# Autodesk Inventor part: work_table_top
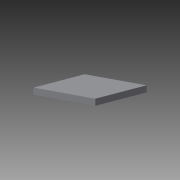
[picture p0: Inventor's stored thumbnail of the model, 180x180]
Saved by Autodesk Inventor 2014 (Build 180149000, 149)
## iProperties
Created: 2008-06
Part Number: work_table_top
Document SubType Name: Modeling
Designer: Autodesk
Density: 1 g/cm^3
Material: Generic
Appearance: Default
Author: Autodesk
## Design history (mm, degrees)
sketch "Sketch1"
  geometry: L1 (0, 0)-(1000, 0); L2 (1000, 0)-(1000, 90); L3 (1000, 90)-(0, 90); L4 (0, 90)-(0, 0)
  constraints: 8 end point, 2 parallel, 1 horizontal, 1 perpendicular
  dimensions: "d0" = 1000 distance of L2.end L3.end; "d1" = 90 distance of L3.end L1.start
extrude "Extrusion1" new body sketch "Sketch1" distance "d2" = 1000; taper "d3" = 0 deg
body "Solid1"
